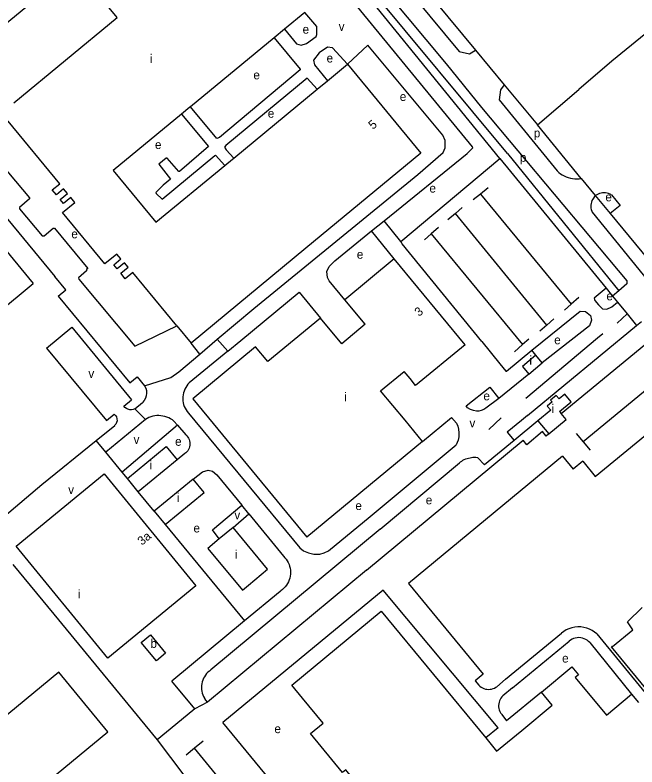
# Model space of a CAD drawing. Extents: x 156097 to 158136, y 385644 to 388348.
# Drawn here: x 157019.8 to 157303.6, y 386635.8 to 386978.7 of the extents above; entities that cross this region are included whole.
import ezdxf

# ---------------------------------------------------------------- set-up
doc = ezdxf.new("R2010")
doc.units = 0
for name, color, linetype in [('BLT_Basislijn', 7, 'Continuous'), ('BLT_Bebouwing', 7, 'Continuous'), ('BLT_Centroide', 7, 'Continuous'), ('BLT_Huisnummer', 7, 'Continuous'), ('BLT_Huisnummer_reeks', 7, 'Continuous'), ('BLT_Vlakafsluiter', 7, 'Continuous')]:
    doc.layers.add(name, color=color, linetype=linetype)

msp = doc.modelspace()

# ---------------------------------------------------------------- linework, layer by layer
at = {"layer": 'BLT_Basislijn'}
for p, q in [((157335.94, 386993.39), (157292.12, 386957.75)), ((157229.92, 386962.68), (157242.99, 386946.93)), ((157292.12, 386957.75), (157277.03, 386944.77)), ((157244.51, 386915.6), (157295.37, 386853.02)), ((156981.2, 386912.78), (157028.02, 386856.23)), ((157278.14, 386904.19), (157284.53, 386896.42)), ((157235.75, 386899.9), (157232.16, 386897.04)), ((157232.16, 386897.04), (157228.87, 386894.43)), ((157232.16, 386897.04), (157273.57, 386846.83)), ((157284.53, 386896.42), (157291.3, 386888.19)), ((157220.71, 386888.27), (157217.33, 386885.32)), ((157223.81, 386890.99), (157220.71, 386888.27)), ((157262.45, 386837.3), (157220.71, 386888.27)), ((157283.2, 386888.8), (157315.99, 386848.3)), ((157195.9, 386875.51), (157188.15, 386884.92)), ((157213.08, 386881.87), (157209.74, 386878.95)), ((157192.85, 386867.51), (157182.47, 386880.32)), ((157209.74, 386878.95), (157206.6, 386876.2)), ((157209.74, 386878.95), (157251.38, 386828.4)), ((157005.2, 386837.49), (157028.02, 386856.23)), ((157289.5, 386854.13), (157292.45, 386850.54)), ((157039.51, 386850.55), (157072.17, 386810.92)), ((157295.37, 386853.02), (157292.45, 386850.54)), ((157292.45, 386850.54), (157294.72, 386847.76)), ((157277.04, 386849.87), (157273.57, 386846.83)), ((157294.72, 386847.76), (157299.13, 386842.39)), ((157273.57, 386846.83), (157270.57, 386844.2)), ((157265.71, 386840.15), (157262.45, 386837.3)), ((157299.13, 386842.39), (157294.62, 386838.27)), ((157299.13, 386842.39), (157303.44, 386837.13)), ((157253.62, 386796.06), (157303.44, 386837.13)), ((157262.45, 386837.3), (157259.23, 386834.48)), ((157303.44, 386837.13), (157305.73, 386839.01)), ((157034.19, 386826.84), (157045.64, 386836.31)), ((157045.64, 386836.31), (157072.92, 386803.21)), ((157104.07, 386824.06), (157112.08, 386830.83)), ((157116.92, 386825.45), (157122.83, 386830.35)), ((157254.17, 386830.84), (157251.38, 386828.4)), ((157034.19, 386826.84), (157061.45, 386793.76)), ((157104.07, 386824.06), (157100.14, 386829.08)), ((157232.78, 386829.79), (157241.02, 386819.69)), ((157251.38, 386828.4), (157247.69, 386825.17)), ((157268.95, 386796.97), (157307.63, 386828.85)), ((157116.92, 386825.45), (157099.27, 386810.97)), ((157257.42, 386823.67), (157255.64, 386825.82)), ((157072.17, 386810.92), (157075.56, 386813.71)), ((157075.56, 386813.71), (157078.91, 386809.65)), ((157254.22, 386814.97), (157240.61, 386803.83)), ((157313.65, 386812.61), (157279.03, 386784.08)), ((157069.45, 386800.36), (157072.92, 386803.21)), ((157284.55, 386768.31), (157328.03, 386804.15)), ((157074.42, 386799.13), (157077.95, 386802.04)), ((157061.45, 386793.76), (157064.99, 386796.68)), ((157253.62, 386796.06), (157250.95, 386793.78)), ((157079.3, 386794.3), (157061.13, 386779.33)), ((157092.29, 386793.48), (157093.84, 386791.7)), ((157235.94, 386789.77), (157241.65, 386795)), ((157250.95, 386793.78), (157244.31, 386788.54)), ((157258.41, 386793.61), (157247.49, 386784.67)), ((157056.78, 386784.72), (157065.23, 386791.55)), ((157093.84, 386791.7), (157068.58, 386770.29)), ((157093.84, 386791.7), (157097.71, 386787.27)), ((157260.51, 386788.74), (157253.27, 386782.77)), ((157262.2, 386786.7), (157260.51, 386788.74)), ((157244.31, 386788.54), (157247.49, 386784.67)), ((157263.37, 386787.66), (157262.2, 386786.7)), ((157275.85, 386787.94), (157279.03, 386784.08)), ((157061.13, 386779.33), (157056.78, 386784.72)), ((157180.16, 386725.56), (157251.6, 386784.81)), ((157181.8, 386750), (157221.1, 386782.77)), ((157247.49, 386784.67), (157233.97, 386773.53)), ((157253.27, 386782.77), (157251.6, 386784.81)), ((157279.03, 386784.08), (157282.21, 386780.22)), ((157068.58, 386770.29), (157061.13, 386779.33)), ((157097.3, 386778.76), (157093.79, 386775.93)), ((157269.66, 386777.54), (157199.26, 386719.52)), ((157230.76, 386776.99), (157233.97, 386773.53)), ((157269.66, 386777.54), (157274.5, 386771.68)), ((157278.83, 386775.24), (157274.5, 386771.68)), ((157278.83, 386775.24), (157284.55, 386768.31)), ((157186.45, 386744.25), (157222.53, 386774.54)), ((157071.02, 386767.34), (157068.58, 386770.29)), ((157083.32, 386752.42), (157076.01, 386761.28)), ((157126.42, 386751.31), (157123.2, 386755.23)), ((157119.24, 386744.99), (157126.42, 386751.31)), ((157126.42, 386751.31), (157142.3, 386731.9)), ((157088.32, 386746.36), (157124.54, 386702.47)), ((157018.83, 386728.12), (157037.44, 386705.49)), ((157180.16, 386725.56), (157107.57, 386665.35)), ((157199.26, 386719.52), (157233.43, 386678.14)), ((157187.82, 386716.41), (157114.65, 386656.11)), ((157140.69, 386715.85), (157124.54, 386702.47)), ((157240.24, 386653.72), (157187.82, 386716.41)), ((157037.44, 386705.49), (157084.61, 386648.15)), ((157124.54, 386702.47), (157091.39, 386674.99)), ((157243.64, 386675.82), (157269.2, 386696.89)), ((157285.21, 386696.53), (157307.37, 386669.67)), ((157246.78, 386671.92), (157272.7, 386693.25)), ((157282.05, 386692.58), (157301.08, 386668.97)), ((157233.43, 386678.14), (157229.74, 386675.1)), ((157239.6, 386672.4), (157243.64, 386675.82)), ((157101.85, 386662.26), (157091.39, 386674.99)), ((157229.74, 386675.1), (157231.39, 386673.08)), ((157246.78, 386671.92), (157242.42, 386668.26)), ((157259.97, 386670), (157244.04, 386656.86)), ((157106.79, 386666.31), (157106.34, 386667.03)), ((157107.57, 386665.35), (157106.79, 386666.31)), ((157101.85, 386662.26), (157093.18, 386655.16)), ((157241.87, 386659.79), (157244.04, 386656.86)), ((157093.18, 386655.16), (157084.61, 386648.15)), ((157152.67, 386610.07), (157114.65, 386656.11)), ((157240.24, 386653.72), (157234.58, 386649.06)), ((157084.61, 386648.15), (157096.77, 386632.13)), ((157105.55, 386647.55), (157101.69, 386644.37)), ((157101.69, 386644.37), (157097.84, 386641.19)), ((157141.58, 386595.98), (157101.69, 386644.37))]:
    msp.add_line(p, q, dxfattribs=at)
for points in [[(157188.15, 386884.92), (157226.06, 386915.59), (157228.61, 386918.1), (157228.51, 386918.57), (157120.99, 387049.68), (157082.22, 387097.44), (157081.91, 387098.46)], [(157140.07, 387078.66), (157146.77, 387070.58), (157148.22, 387061.17), (157229.92, 386962.68)], [(157135.44, 387066.9), (157222.47, 386962.04)], [(157241.01, 386913.29), (157155.11, 387018.88), (157129.1, 387050.39)], [(157244.51, 386915.6), (157182.04, 386990.86)], [(157189.44, 386989.01), (157216.47, 386956.48), (157232.57, 386936.49)], [(157142.74, 386972.25), (157148.27, 386965.6), (157150.27, 386964.96), (157152.82, 386965.66), (157157.18, 386968.87), (157157.54, 386969.83), (157157.44, 386973.44), (157151.96, 386979.86)], [(157137.99, 386968.34), (157149.95, 386954.04), (157149.95, 386953.72), (157113.11, 386922.8), (157111.84, 386922.44), (157099.79, 386936.84)], [(157112.08, 386830.83), (157128.7, 386844.85), (157203.52, 386906.02), (157215.08, 386916.06), (157216.04, 386918.19), (157216.04, 386921.53), (157214.92, 386923.92), (157180.81, 386964.93), (157171.5, 386956.29)], [(157171.5, 386956.29), (157164.67, 386963.82), (157162.36, 386964.09), (157158.61, 386961.43), (157156, 386958.18), (157156.38, 386955.96), (157162.3, 386948.7)], [(157222.47, 386962.04), (157227.14, 386961.02), (157229.92, 386962.68)], [(157157.69, 386944.9), (157153.14, 386949.98), (157115.97, 386919.24), (157115.34, 386918.45), (157116.18, 386917.18), (157119.55, 386913.45)], [(157242.99, 386946.93), (157241.37, 386944.54), (157240.69, 386940.03)], [(157242.99, 386946.93), (157258.2, 386928.59)], [(157258.2, 386928.59), (157277.03, 386944.77)], [(157240.69, 386940.03), (157267.21, 386907.64), (157267.91, 386906.98), (157268.7, 386906.36), (157269.52, 386905.81), (157270.39, 386905.33), (157271.3, 386904.92), (157272.24, 386904.58), (157273.2, 386904.32), (157274.17, 386904.13), (157275.16, 386904.03), (157276.16, 386904), (157277.15, 386904.06), (157278.14, 386904.19)], [(157232.57, 386936.49), (157298.99, 386857.57)], [(157095.79, 386933.54), (157108.02, 386918.83), (157094.88, 386907.37), (157094.56, 386907.41), (157089.25, 386913.39), (157088.68, 386913.51), (157085.43, 386910.71), (157090.68, 386903.94), (157087.34, 386901.17), (157084, 386897.83), (157084.15, 386897.3), (157086.86, 386894.71), (157110.93, 386914.68), (157111.2, 386914.75), (157115.46, 386910.08)], [(157016.68, 386930.34), (157003.5, 386919.46), (157002.66, 386917.97), (157002.61, 386914.85), (157005.23, 386911.48), (157005.83, 386911.54), (157007.25, 386912.78), (157010.18, 386914.37), (157026.41, 386895.28), (157026.41, 386894.96), (157021.75, 386890.92), (157021.84, 386890.29), (157032.14, 386878.1), (157032.98, 386878.06), (157037.23, 386881.57), (157037.71, 386881.53), (157052.98, 386863.15), (157052.4, 386862.6), (157052.34, 386862.06), (157048.68, 386858.85), (157048.84, 386858.28), (157074.5, 386827.65), (157093.59, 386837.01)], [(157278.14, 386904.19), (157258.2, 386928.59)], [(156981.2, 386912.78), (156983.67, 386914.73), (156987.37, 386915.95), (156990.35, 386915.43), (156992.74, 386913.98), (157037.87, 386859.45)], [(157195.9, 386875.51), (157241.01, 386913.29)], [(157241.01, 386913.29), (157289.5, 386854.13)], [(157284.53, 386896.42), (157283.38, 386894.71), (157283.06, 386894.1), (157282.81, 386893.45), (157282.63, 386892.77), (157282.54, 386892.08), (157282.52, 386891.38), (157282.59, 386890.69), (157282.73, 386890.01), (157282.95, 386889.34), (157283.2, 386888.8)], [(157291.9, 386896.7), (157291.3, 386897.04), (157290.65, 386897.32), (157289.99, 386897.51), (157289.3, 386897.63), (157288.6, 386897.67), (157287.91, 386897.63), (157287.22, 386897.52), (157286.55, 386897.32), (157285.91, 386897.05), (157285.3, 386896.7), (157284.53, 386896.42)], [(157291.9, 386896.7), (157295.95, 386891.84), (157291.3, 386888.19)], [(157291.3, 386888.19), (157323.88, 386848.91)], [(157182.47, 386880.32), (157188.15, 386884.92)], [(157168.98, 386869.4), (157182.47, 386880.32)], [(157232.78, 386829.79), (157196.44, 386874.36), (157195.9, 386875.51)], [(157170.31, 386848.91), (157163.18, 386857.48), (157162.38, 386859.01), (157162.07, 386861.74), (157163.11, 386864), (157165.63, 386866.64), (157168.98, 386869.4)], [(157039.51, 386850.55), (157042.87, 386853.38), (157037.87, 386859.45)], [(157298.99, 386857.57), (157299.01, 386856.11), (157295.37, 386853.02)], [(157289.5, 386854.13), (157284.04, 386849.67), (157284.36, 386848.6), (157286.07, 386846.58), (157287.9, 386844.8), (157289.86, 386844.64), (157292.18, 386845.72), (157294.72, 386847.76)], [(157122.83, 386830.35), (157149.37, 386852.38), (157159.21, 386840.48)], [(157255.64, 386825.82), (157277.67, 386843.74), (157280.16, 386843.58), (157282.31, 386841.69), (157282.9, 386839.54), (157281.9, 386837.01), (157260.35, 386820.13)], [(157288.07, 386833.31), (157285.56, 386831.4), (157252.88, 386803.8)], [(157090.82, 386813.4), (157094.54, 386816.03), (157104.07, 386824.06)], [(157241.02, 386819.69), (157243.72, 386816.38), (157244.04, 386816.38), (157255.64, 386825.82)], [(157078.91, 386809.65), (157079.38, 386808.63), (157079.68, 386807.5), (157079.76, 386806.3), (157079.61, 386805.09), (157079.23, 386803.94), (157078.67, 386802.91), (157077.95, 386802.04)], [(157099.27, 386810.97), (157098.66, 386810.31), (157098.12, 386809.6), (157097.64, 386808.85), (157097.23, 386808.05), (157096.89, 386807.22), (157096.63, 386806.37), (157096.45, 386805.49), (157096.34, 386804.61), (157096.31, 386803.71), (157096.37, 386802.82), (157096.5, 386801.93), (157096.71, 386801.07), (157097, 386800.22), (157097.37, 386799.4), (157097.8, 386798.62), (157098.3, 386797.88), (157098.87, 386797.19), (157149.67, 386735.75)], [(157240.61, 386803.83), (157234.66, 386799.48), (157233.75, 386798.87), (157232.51, 386798.37), (157231.45, 386798.09), (157230.39, 386798.09), (157228.98, 386798.32), (157227.69, 386798.87), (157226.32, 386799.64), (157225.65, 386800.46), (157236.5, 386809.04)], [(157236.5, 386809.04), (157240.61, 386803.83)], [(157074.42, 386799.13), (157073.71, 386798.84), (157072.93, 386798.7), (157072.1, 386798.72), (157071.3, 386798.92), (157070.56, 386799.29), (157069.94, 386799.78), (157069.45, 386800.36)], [(157064.99, 386796.68), (157065.55, 386796.15), (157066, 386795.45), (157066.27, 386794.62), (157066.31, 386793.73), (157066.12, 386792.87), (157065.73, 386792.13), (157065.22, 386791.56)], [(157092.29, 386793.48), (157091.55, 386794.05), (157090.76, 386794.56), (157089.93, 386794.99), (157089.07, 386795.36), (157088.18, 386795.65), (157087.27, 386795.86), (157086.34, 386795.99), (157085.4, 386796.05), (157084.47, 386796.02), (157083.54, 386795.92), (157082.62, 386795.73), (157081.72, 386795.47), (157080.85, 386795.13), (157080.01, 386794.72), (157079.3, 386794.3)], [(157205.71, 386784.21), (157218.94, 386795.17), (157221.16, 386792.53), (157221.77, 386791.2), (157222.15, 386789.79), (157222.35, 386788.25), (157222.28, 386786.41), (157221.93, 386784.86), (157221.1, 386782.77)], [(157097.71, 386787.27), (157098.18, 386786.8), (157098.58, 386786.28), (157098.92, 386785.71), (157099.19, 386785.1), (157099.39, 386784.47), (157099.5, 386783.82), (157099.54, 386783.16), (157099.49, 386782.49), (157099.37, 386781.84), (157099.17, 386781.21), (157098.9, 386780.61), (157098.55, 386780.04), (157098.14, 386779.52), (157097.67, 386779.06), (157097.3, 386778.76)], [(156977.7, 386718.78), (157032.01, 386764.67), (157056.78, 386784.72)], [(157222.53, 386774.54), (157223.05, 386774.95), (157223.61, 386775.32), (157224.19, 386775.67), (157224.8, 386775.98), (157225.42, 386776.26), (157226.07, 386776.5), (157226.73, 386776.69), (157227.4, 386776.85), (157228.07, 386776.96), (157228.75, 386777.03), (157229.43, 386777.06), (157230.1, 386777.05), (157230.76, 386776.99)], [(157101.09, 386767.08), (157105.33, 386770.45), (157107.93, 386771.23), (157109.93, 386770.72), (157111.84, 386768.97), (157123.2, 386755.23)], [(157112.98, 386739.81), (157109.93, 386743.95), (157123.2, 386755.23)], [(157149.67, 386735.75), (157151.41, 386734.36), (157153.64, 386733.45), (157156.19, 386732.91), (157158.81, 386732.84), (157160.83, 386733.4), (157162.76, 386734.36), (157181.8, 386750)], [(157186.45, 386744.25), (157109.11, 386680.09), (157108.47, 386679.54)], [(157142.3, 386731.9), (157142.92, 386731.24), (157143.49, 386730.54), (157143.99, 386729.79), (157144.43, 386729), (157144.79, 386728.17), (157145.07, 386727.31), (157145.28, 386726.43), (157145.42, 386725.54), (157145.47, 386724.64), (157145.44, 386723.73), (157145.33, 386722.84), (157145.15, 386721.95), (157144.88, 386721.09), (157144.54, 386720.25), (157144.13, 386719.45), (157143.65, 386718.68), (157143.1, 386717.96), (157142.49, 386717.29), (157141.83, 386716.68), (157141.11, 386716.13), (157140.69, 386715.85)], [(157285.21, 386696.53), (157284.25, 386697.32), (157283.16, 386698.04), (157281.98, 386698.65), (157280.7, 386699.14), (157279.36, 386699.48), (157277.98, 386699.68), (157276.57, 386699.71), (157275.18, 386699.58), (157273.82, 386699.29), (157272.53, 386698.87), (157271.32, 386698.31), (157270.2, 386697.65), (157269.2, 386696.89)], [(157282.05, 386692.58), (157281.52, 386693.09), (157280.92, 386693.57), (157280.25, 386693.98), (157279.52, 386694.32), (157278.74, 386694.57), (157277.92, 386694.74), (157277.09, 386694.8), (157276.26, 386694.75), (157275.45, 386694.61), (157274.68, 386694.38), (157273.96, 386694.07), (157273.29, 386693.69), (157272.7, 386693.25)], [(157108.47, 386679.54), (157107.81, 386678.99), (157107.21, 386678.37), (157106.66, 386677.71), (157106.18, 386676.99), (157105.76, 386676.24), (157105.42, 386675.44), (157105.15, 386674.62), (157104.96, 386673.78), (157104.84, 386672.93), (157104.81, 386672.07), (157104.86, 386671.21), (157104.98, 386670.35), (157105.19, 386669.51), (157105.47, 386668.7), (157105.83, 386667.91), (157106.25, 386667.16), (157106.34, 386667.03)], [(157231.39, 386673.08), (157231.91, 386672.6), (157232.49, 386672.18), (157233.1, 386671.84), (157233.76, 386671.56), (157234.44, 386671.36), (157235.13, 386671.23), (157235.84, 386671.19), (157236.55, 386671.22), (157237.25, 386671.34), (157237.93, 386671.53), (157238.59, 386671.8), (157239.21, 386672.14), (157239.6, 386672.4)], [(157242.42, 386668.26), (157241.93, 386667.75), (157241.5, 386667.2), (157241.14, 386666.6), (157240.85, 386665.96), (157240.63, 386665.29), (157240.49, 386664.61), (157240.43, 386663.91), (157240.45, 386663.21), (157240.55, 386662.51), (157240.73, 386661.84), (157240.98, 386661.18), (157241.31, 386660.56), (157241.71, 386659.98), (157241.87, 386659.79)]]:
    msp.add_lwpolyline(points, dxfattribs=at)
at = {"layer": 'BLT_Bebouwing'}
for p, q in [((157019.2, 386938.68), (157066.37, 386977.57)), ((157151.96, 386979.86), (157142.74, 386972.25)), ((157142.74, 386972.25), (157137.99, 386968.34)), ((157137.99, 386968.34), (157099.79, 386936.84)), ((157162.3, 386948.7), (157171.5, 386956.29)), ((157157.69, 386944.9), (157162.3, 386948.7)), ((157119.55, 386913.45), (157157.69, 386944.9)), ((157099.58, 386936.67), (157095.79, 386933.54)), ((157099.79, 386936.84), (157099.58, 386936.67)), ((157095.79, 386933.54), (157064.59, 386907.81)), ((157115.46, 386910.08), (157119.05, 386913.04)), ((157119.05, 386913.04), (157119.55, 386913.45)), ((157084.06, 386884.19), (157115.46, 386910.08)), ((157064.59, 386907.81), (157084.06, 386884.19)), ((157152.48, 386872.43), (157100.14, 386829.08)), ((157192.85, 386867.51), (157170.31, 386848.91)), ((157225.13, 386828.39), (157192.85, 386867.51)), ((157179.55, 386837.69), (157170.31, 386848.91)), ((157093.59, 386837.01), (157100.14, 386829.08)), ((157225.13, 386828.39), (157202.57, 386809.79)), ((157254.22, 386814.97), (157260.35, 386820.13)), ((157268.22, 386797.85), (157268.95, 386796.97)), ((157205.71, 386784.21), (157197.74, 386794.03)), ((157258.41, 386793.61), (157263.37, 386787.66)), ((157205.71, 386784.21), (157153, 386740.63)), ((157093.79, 386775.93), (157076.01, 386761.28)), ((157020.27, 386736.44), (157060.43, 386769.49)), ((157060.43, 386769.49), (157102.28, 386718.46)), ((157076.01, 386761.28), (157071.02, 386767.34)), ((157101.09, 386767.08), (157083.32, 386752.42)), ((157119.24, 386744.99), (157112.98, 386739.81)), ((157062.15, 386685.46), (157020.27, 386736.44)), ((157102.28, 386718.46), (157062.15, 386685.46)), ((157123.52, 386716.48), (157126.28, 386718.76)), ((157244.47, 386647.14), (157250.97, 386652.5))]:
    msp.add_line(p, q, dxfattribs=at)
for points in [[(157066.37, 386977.57), (157047.13, 387000.88), (157000.31, 386962.25)], [(157171.5, 386956.29), (157205.01, 386915.68), (157152.48, 386872.43)], [(157047.07, 386893.24), (157045.19, 386895.52), (157041.86, 386892.78), (157040.34, 386894.62), (157043.64, 386897.34), (157041.94, 386899.4), (157038.64, 386896.68), (157036.77, 386898.95), (157040.17, 386901.75), (157016.68, 386930.34)], [(157066.21, 386869.74), (157060.76, 386865.25), (157041.48, 386888.63), (157047.07, 386893.24)], [(157093.59, 386837.01), (157073.47, 386861.3), (157070.05, 386858.48), (157068.02, 386860.94), (157071.35, 386863.68), (157069.73, 386865.66), (157066.41, 386862.92), (157064.81, 386864.86), (157068.03, 386867.52), (157066.21, 386869.74)], [(157159.21, 386840.48), (157135.17, 386820.66), (157129.57, 386827.41), (157100.9, 386803.65), (157153, 386740.63)], [(157179.55, 386837.69), (157168.84, 386828.84), (157159.21, 386840.48)], [(157257.42, 386823.67), (157251.28, 386818.51), (157254.22, 386814.97)], [(157260.35, 386820.13), (157257.42, 386823.67)], [(157197.74, 386794.03), (157186.62, 386807.33), (157197.3, 386816.16)], [(157202.57, 386809.79), (157200.04, 386813), (157197.3, 386816.16)], [(157266.75, 386805.24), (157264.14, 386803.08), (157264.83, 386802.25), (157262.6, 386800.4), (157264.22, 386798.45), (157258.41, 386793.61)], [(157268.22, 386797.85), (157273.56, 386802.29), (157270.66, 386805.79), (157268.07, 386803.65), (157266.75, 386805.24)], [(157263.37, 386787.66), (157271.24, 386794.22), (157268.95, 386796.97)], [(157071.02, 386767.34), (157088.79, 386782), (157093.79, 386775.93)], [(157088.32, 386746.36), (157106.09, 386761.05), (157101.09, 386767.08)], [(157083.32, 386752.42), (157088.32, 386746.36)], [(157126.28, 386718.76), (157134.98, 386725.96), (157119.24, 386744.99)], [(157112.98, 386739.81), (157107.78, 386735.51), (157123.52, 386716.48)], [(157150.91, 386667.21), (157146.01, 386673.15), (157186.92, 386706.88), (157234.58, 386649.06)], [(157301.75, 386698.38), (157299.33, 386702.03), (157305.99, 386708.58)], [(157292, 386690.67), (157292.25, 386690.88), (157292.37, 386690.73), (157301.75, 386698.38)], [(157088.38, 386687.69), (157084.25, 386684.29), (157077.38, 386692.61), (157081.51, 386696.02), (157088.38, 386687.69)], [(157311.95, 386666.4), (157292, 386690.67)], [(157039.69, 386679.08), (157008.89, 386653.73), (156993.01, 386673.02), (156969.52, 386653.68), (157006.07, 386609.22), (157002.5, 386606.28), (157004.19, 386604.23), (156988.5, 386591.31), (156998.23, 386579.49), (157002.08, 386582.67), (157025.46, 386601.92), (157015.82, 386613.63), (157062.16, 386651.78), (157039.69, 386679.08)], [(157259.97, 386670), (157273.93, 386681.49)], [(157273.93, 386681.49), (157276.89, 386677.87), (157275.41, 386676.67), (157289.61, 386659.51), (157301.08, 386668.97)], [(157250.97, 386652.5), (157264.92, 386664), (157259.97, 386670)], [(157301.08, 386668.97), (157304.24, 386665.14)], [(157168.08, 386622.97), (157175.3, 386628.92), (157170.68, 386634.51), (157169.27, 386633.34), (157154.66, 386651.06), (157160.35, 386655.75), (157150.91, 386667.21)], [(157234.58, 386649.06), (157239.53, 386643.07), (157244.47, 386647.14)]]:
    msp.add_lwpolyline(points, dxfattribs=at)
at = {"layer": 'BLT_Vlakafsluiter'}
for p, q in [((157116.92, 386825.45), (157112.08, 386830.83)), ((157078.91, 386809.65), (157090.82, 386813.4)), ((157074.42, 386799.13), (157079.3, 386794.3)), ((157107.57, 386665.35), (157101.85, 386662.26))]:
    msp.add_line(p, q, dxfattribs=at)

# ---------------------------------------------------------------- texts
at = {"layer": 'BLT_Centroide'}
for s, p in [('v', (157167.46, 386971.51)), ('e', (157150.98, 386970.23)), ('i', (157081.3, 386956.84)), ('e', (157161.93, 386957.08)), ('e', (157128.52, 386949.41)), ('e', (157195.34, 386939.55)), ('e', (157135.1, 386931.88)), ('p', (157256.51, 386922.94)), ('e', (157083.61, 386917.63)), ('p', (157250.15, 386911.79)), ('e', (157208.88, 386897.76)), ('e', (157289.15, 386893.77)), ('e', (157045.44, 386876.91)), ('e', (157175.74, 386867.59)), ('e', (157289.62, 386848.62)), ('e', (157265.81, 386828.58)), ('i', (157254.49, 386819.31)), ('v', (157053.23, 386813.25)), ('i', (157169.97, 386802.62)), ('e', (157233.5, 386803.04)), ('i', (157264.65, 386797.22)), ('v', (157227.15, 386790.69)), ('v', (157073.85, 386783.16)), ('e', (157092.79, 386782.29)), ('i', (157081.13, 386771.47)), ('v', (157044.02, 386760.32)), ('i', (157093.58, 386756.69)), ('e', (157207.19, 386755.58)), ('e', (157175.07, 386753)), ('v', (157119.87, 386748.78)), ('e', (157101.19, 386742.76)), ('i', (157120.04, 386730.73)), ('i', (157048.39, 386712.64)), ('b', (157081.54, 386690.14)), ('e', (157269.42, 386683.43)), ('e', (157138.13, 386651.24))]:
    msp.add_text(s, height=4, dxfattribs=at).set_placement(p)
at = {"layer": 'BLT_Huisnummer'}
for s, p in [('3', (157204.1, 386841.02)), ('3a', (157077.67, 386736.67))]:
    msp.add_text(s, height=4, rotation=39.4645, dxfattribs=at).set_placement(p)
at = {"layer": 'BLT_Huisnummer_reeks'}
msp.add_text('5', height=4, rotation=39.4645, dxfattribs=at).set_placement((157183.05, 386926.32))

doc.saveas('drawing.dxf')
